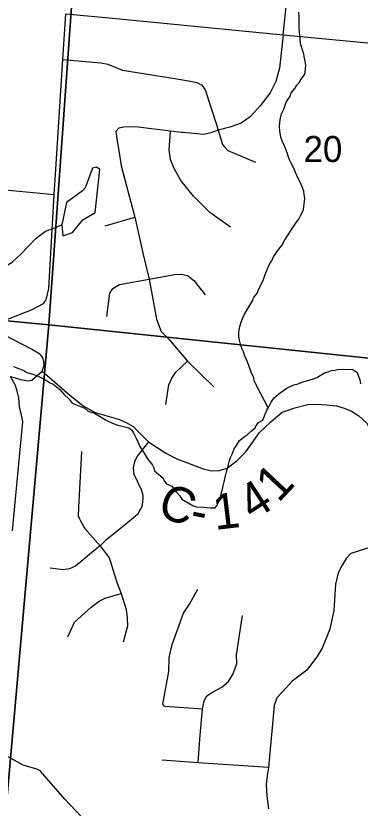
# Model space of a CAD drawing. Extents: x 0 to 34, y -2 to 22.
# Drawn here: x 3.329 to 3.881, y 18.207 to 19.479 of the extents above; entities that cross this region are included whole.
import ezdxf

# ---------------------------------------------------------------- set-up
doc = ezdxf.new("R2010")
doc.units = 0
for name, color, linetype in [('GM_X_County_Road', 7, 'Continuous'), ('GM_X_County_Road_Text', 7, 'Continuous'), ('GM_X_Minor_Lake', 7, 'Continuous'), ('GM_X_Minor_River', 7, 'Continuous'), ('GM_X_Section', 7, 'Continuous'), ('GM_X_Section_Text', 7, 'Continuous'), ('GM_X_Township_Road', 7, 'Continuous')]:
    doc.layers.add(name, color=color, linetype=linetype)

msp = doc.modelspace()

# ---------------------------------------------------------------- linework, layer by layer
at = {"layer": 'GM_X_County_Road'}
for p, q in [((3.4093, 19.4828), (3.4788, 19.4761)), ((3.4788, 19.4761), (3.7574, 19.4492))]:
    msp.add_line(p, q, dxfattribs=at)
for points in [[(3.3764, 19.0222), (3.3785, 19.0257), (3.382, 19.0419), (3.3907, 19.1924), (3.3925, 19.2247), (3.4045, 19.4092), (3.4093, 19.4828)], [(3.7574, 19.4492), (3.7687, 19.4481), (3.9381, 19.4318), (4.0026, 19.4257), (4.0072, 19.4252), (4.0934, 19.4164), (4.1461, 19.4103), (4.1935, 19.4056), (4.2871, 19.3945), (4.3454, 19.3876), (4.3544, 19.3865)], [(3.2954, 18.9847), (3.2957, 18.9857), (3.298, 18.9872), (3.3198, 18.9941), (3.3543, 19.0075), (3.3733, 19.0175), (3.3749, 19.0196), (3.3759, 19.0213), (3.3764, 19.0222)], [(3.3715, 18.9091), (3.3743, 18.9185), (3.374, 18.9246), (3.3728, 18.9294), (3.3698, 18.934), (3.3693, 18.9347), (3.3678, 18.9363), (3.3542, 18.9444), (3.2968, 18.974), (3.2952, 18.9755), (3.295, 18.9775), (3.2948, 18.9828), (3.2951, 18.9838), (3.2954, 18.9847)], [(3.3205, 18.9003), (3.3385, 18.8951), (3.3495, 18.8937), (3.3545, 18.8947), (3.3715, 18.9091)], [(3.3715, 18.9091), (3.383, 18.8987), (3.4151, 18.871), (3.4368, 18.8533), (3.4563, 18.8427), (3.4934, 18.832), (3.5061, 18.8267), (3.517, 18.8203), (3.5285, 18.809), (3.5418, 18.7955), (3.5694, 18.7772), (3.5873, 18.7682), (3.6309, 18.7519), (3.6432, 18.7489), (3.6549, 18.7495), (3.6679, 18.7535), (3.6839, 18.7655), (3.6976, 18.7795), (3.7195, 18.8103), (3.7365, 18.8263), (3.7378, 18.8276), (3.7421, 18.8312)], [(3.324, 18.6527), (3.3401, 18.8282), (3.3382, 18.8386), (3.3352, 18.8516), (3.3338, 18.866), (3.3315, 18.8768), (3.3284, 18.886), (3.3205, 18.9003)], [(3.7421, 18.8312), (3.7562, 18.843), (3.7765, 18.8503), (3.7971, 18.8553), (3.8116, 18.856), (3.8271, 18.8551), (3.8429, 18.8535), (3.8553, 18.8497), (3.8669, 18.8447), (3.8788, 18.8371), (3.8917, 18.8257), (3.9038, 18.8021), (3.9148, 18.7904), (3.9229, 18.7837), (3.9307, 18.7777), (3.9401, 18.7751), (3.9526, 18.7757), (3.9665, 18.7827), (3.9977, 18.799)], [(3.4549, 18.1718), (3.4521, 18.1749), (3.4075, 18.2217), (3.3688, 18.2666), (3.3673, 18.2678), (3.3628, 18.2699), (3.3411, 18.2766), (3.3169, 18.29)]]:
    msp.add_lwpolyline(points, dxfattribs=at)
at = {"layer": 'GM_X_Minor_Lake'}
for points in [[(3.4199, 19.1315), (3.4364, 19.1519), (3.4561, 19.1636), (3.4636, 19.2329), (3.4584, 19.2365), (3.4519, 19.2348), (3.4417, 19.2077), (3.4404, 19.2031), (3.4358, 19.1987), (3.4102, 19.18), (3.4031, 19.1439)], [(3.4031, 19.1439), (3.4042, 19.1262), (3.4199, 19.1315)]]:
    msp.add_lwpolyline(points, dxfattribs=at)
at = {"layer": 'GM_X_Minor_River'}
for points in [[(3.7335, 18.85), (3.7152, 18.8851), (3.7113, 18.8939), (3.7104, 18.8985), (3.7065, 18.9074), (3.703, 18.9163), (3.6999, 18.9251), (3.6964, 18.9332), (3.6939, 18.9398), (3.6918, 18.9444), (3.6897, 18.9502), (3.6874, 18.9586), (3.6864, 18.964), (3.6867, 18.9708), (3.6881, 18.9806), (3.6903, 18.9878), (3.6924, 18.9934), (3.6952, 18.9994), (3.6981, 19.005), (3.7041, 19.0151), (3.7089, 19.0225), (3.7102, 19.0266), (3.7162, 19.0348), (3.7183, 19.04), (3.7231, 19.049), (3.726, 19.0561), (3.7286, 19.064), (3.7336, 19.076), (3.7364, 19.082), (3.7392, 19.0861), (3.7421, 19.0924), (3.7469, 19.0995), (3.7509, 19.1047), (3.7553, 19.111), (3.7605, 19.1199), (3.7669, 19.1292), (3.7722, 19.1381), (3.7786, 19.1474), (3.7825, 19.153), (3.7858, 19.1597), (3.7903, 19.1683), (3.7909, 19.1736), (3.7919, 19.1812), (3.7921, 19.1865), (3.7915, 19.1926), (3.7906, 19.1979), (3.7881, 19.2049), (3.785, 19.2126), (3.7814, 19.2184), (3.7793, 19.223), (3.7772, 19.2281), (3.7748, 19.235), (3.7712, 19.2419), (3.768, 19.247), (3.7659, 19.2524), (3.7638, 19.2593), (3.7597, 19.2705), (3.7561, 19.279), (3.7541, 19.2847), (3.7521, 19.2947), (3.7516, 19.3015), (3.7522, 19.3084), (3.7532, 19.3155), (3.755, 19.3223), (3.7587, 19.3298), (3.7625, 19.3407), (3.7689, 19.3504), (3.7702, 19.3556), (3.7765, 19.3626), (3.7793, 19.3679), (3.7837, 19.373), (3.7873, 19.3794), (3.7905, 19.3834), (3.7929, 19.3879), (3.7936, 19.3947), (3.7937, 19.3997), (3.7928, 19.4065), (3.7919, 19.4115), (3.7906, 19.418), (3.7861, 19.433), (3.7849, 19.4406), (3.7847, 19.4456), (3.7838, 19.4521), (3.783, 19.4624), (3.783, 19.4723), (3.7831, 19.4772), (3.7826, 19.4852)], [(3.1967, 19.076), (3.2167, 19.0801), (3.2277, 19.0809), (3.2402, 19.0802), (3.2508, 19.0772), (3.2639, 19.0726), (3.2763, 19.0681), (3.2896, 19.0654), (3.3026, 19.0715), (3.3123, 19.0773), (3.3231, 19.0839), (3.3372, 19.0968), (3.3493, 19.1097), (3.3615, 19.1223), (3.3766, 19.134), (3.39, 19.1386), (3.4031, 19.1439)], [(3.3256, 18.9164), (3.3417, 18.9102), (3.3465, 18.9066), (3.3563, 18.904), (3.3623, 18.9022), (3.3739, 18.8969), (3.3843, 18.8901), (3.3888, 18.888), (3.3995, 18.8796), (3.4061, 18.8718), (3.4145, 18.8639), (3.4196, 18.8577), (3.4301, 18.8535), (3.4395, 18.8494), (3.445, 18.845), (3.4551, 18.8416), (3.4685, 18.8335), (3.473, 18.8311), (3.4771, 18.8287), (3.4838, 18.8254), (3.4928, 18.8221), (3.5038, 18.8198), (3.5101, 18.818), (3.515, 18.8145), (3.5182, 18.809), (3.5214, 18.8024), (3.5249, 18.7955), (3.5281, 18.7878), (3.5346, 18.7773), (3.5403, 18.7683), (3.545, 18.7621), (3.5479, 18.7578), (3.5501, 18.7536), (3.5514, 18.749), (3.5651, 18.7371), (3.5668, 18.7328), (3.5708, 18.7281), (3.579, 18.7244), (3.5834, 18.7182), (3.5878, 18.7139), (3.5918, 18.7088), (3.595, 18.7033), (3.6055, 18.6977), (3.6107, 18.6944), (3.6148, 18.6924), (3.6189, 18.6911), (3.6303, 18.6907), (3.6412, 18.6896), (3.6485, 18.6893), (3.652, 18.6941), (3.6537, 18.6983), (3.6566, 18.7043), (3.658, 18.7122), (3.6605, 18.7193), (3.6619, 18.7269), (3.6636, 18.7333), (3.665, 18.7408), (3.6668, 18.7472), (3.6689, 18.7551), (3.6711, 18.7634), (3.6733, 18.7706), (3.6757, 18.7758), (3.6791, 18.7844), (3.6827, 18.7896), (3.6875, 18.7975), (3.6949, 18.8037), (3.7, 18.8069), (3.7062, 18.8124), (3.7129, 18.8179), (3.7145, 18.822), (3.7181, 18.8264), (3.7251, 18.8304), (3.7264, 18.8345), (3.7288, 18.8397), (3.7313, 18.8465), (3.7345, 18.8517), (3.7386, 18.8592), (3.7434, 18.8662), (3.7505, 18.8724), (3.7579, 18.8779)], [(3.7579, 18.8779), (3.7625, 18.8811), (3.7745, 18.8868), (3.7818, 18.8888), (3.7891, 18.892), (3.7994, 18.8943), (3.8079, 18.8971), (3.8125, 18.8992), (3.8238, 18.9064), (3.8295, 18.9081), (3.8349, 18.9098), (3.8406, 18.9104), (3.8448, 18.9117), (3.854, 18.9122), (3.8691, 18.9117), (3.8762, 18.9069), (3.8807, 18.8953), (3.8816, 18.8884)]]:
    msp.add_lwpolyline(points, dxfattribs=at)
at = {"layer": 'GM_X_Section'}
for points in [[(3.4541, 19.9967), (3.3818, 18.9832), (2.3398, 19.083), (2.4387, 20.1012)], [(3.4541, 19.9967), (4.4338, 19.8873), (4.3356, 18.8839), (3.3818, 18.9832)], [(2.3398, 19.083), (3.3818, 18.9832), (3.2914, 17.96), (2.2302, 18.1283)], [(4.3356, 18.8839), (4.2197, 17.8557), (3.2914, 17.96), (3.3818, 18.9832)]]:
    msp.add_lwpolyline(points, close=True, dxfattribs=at)
at = {"layer": 'GM_X_Township_Road'}
msp.add_line((3.4721, 19.1423), (3.5196, 19.1562), dxfattribs=at)
for points in [[(3.7574, 19.4492), (3.7634, 19.5046), (3.7674, 19.5258), (3.7662, 19.5389), (3.7591, 19.555), (3.7485, 19.5676), (3.7348, 19.575), (3.7023, 19.5935), (3.692, 19.6131), (3.6904, 19.6215), (3.6899, 19.6322), (3.6927, 19.6411), (3.6975, 19.6517), (3.7039, 19.6585), (3.7131, 19.6642), (3.7384, 19.6715)], [(3.7574, 19.4492), (3.7517, 19.3955), (3.7457, 19.3743), (3.737, 19.3558), (3.7209, 19.3348), (3.7049, 19.3172), (3.6902, 19.3074), (3.672, 19.3009), (3.6534, 19.2958), (3.6419, 19.2918), (3.6304, 19.2892), (3.5966, 19.2923)], [(3.4045, 19.4092), (3.4655, 19.4039), (3.4768, 19.402), (3.5, 19.3921), (3.5841, 19.3788), (3.609, 19.3746), (3.6192, 19.3724), (3.6274, 19.3679), (3.6328, 19.3609), (3.6511, 19.3033), (3.6534, 19.2958), (3.6606, 19.273), (3.6639, 19.2684), (3.669, 19.2632), (3.7132, 19.2447)], [(3.5966, 19.2923), (3.5946, 19.2924), (3.577, 19.2944), (3.5254, 19.3006), (3.5093, 19.3011), (3.5024, 19.3007), (3.4944, 19.2992), (3.4896, 19.2937)], [(3.4896, 19.2937), (3.4914, 19.2783), (3.4941, 19.2631), (3.4978, 19.2389), (3.5196, 19.1562), (3.5334, 19.0965)], [(3.673, 19.14), (3.64, 19.1639), (3.6136, 19.1902), (3.5935, 19.2152), (3.5827, 19.2345), (3.5772, 19.2486), (3.575, 19.2636), (3.577, 19.2944)], [(3.2117, 19.1568), (3.2167, 19.2041), (3.219, 19.2059), (3.2229, 19.2081), (3.226, 19.208), (3.2271, 19.2079), (3.3001, 19.201), (3.3907, 19.1924)], [(3.5334, 19.0965), (3.5426, 19.0568), (3.5543, 18.9927), (3.5622, 18.9727), (3.5739, 18.9609), (3.6041, 18.9251), (3.6463, 18.8836)], [(3.4751, 18.9967), (3.4799, 19.034), (3.4844, 19.0419), (3.495, 19.0481), (3.5426, 19.0568), (3.5834, 19.0644), (3.5944, 19.0646), (3.6043, 19.0624), (3.6146, 19.0546), (3.6323, 19.0316)], [(3.5696, 18.8556), (3.5745, 18.8868), (3.5791, 18.8977), (3.5858, 18.9072), (3.6041, 18.9251)], [(3.5418, 18.7955), (3.5298, 18.7807), (3.5234, 18.7724), (3.5191, 18.7635), (3.5173, 18.7536), (3.5181, 18.7436), (3.5298, 18.7188), (3.5326, 18.7101), (3.5327, 18.7048), (3.5322, 18.6992), (3.5309, 18.6911), (3.5241, 18.6787), (3.5021, 18.6608), (3.494, 18.6541)], [(3.4341, 18.78), (3.4305, 18.7098), (3.4293, 18.6906), (3.4292, 18.6757), (3.4306, 18.6732), (3.433, 18.6688)], [(3.433, 18.6688), (3.4399, 18.6564), (3.4641, 18.6284), (3.4785, 18.6094), (3.4812, 18.6014), (3.4842, 18.5922)], [(3.494, 18.6541), (3.4881, 18.6492), (3.4728, 18.637), (3.4641, 18.6284), (3.4507, 18.6177), (3.4371, 18.6059), (3.4246, 18.5959), (3.4151, 18.5916), (3.4048, 18.5902), (3.384, 18.5928)], [(3.9787, 18.6604), (3.9758, 18.6511), (3.8663, 18.6165), (3.8583, 18.6084), (3.8519, 18.5974), (3.8458, 18.585), (3.8417, 18.5672), (3.839, 18.5245), (3.8326, 18.495), (3.82, 18.4641), (3.8128, 18.4518), (3.7953, 18.4288), (3.7721, 18.4115), (3.7563, 18.3943), (3.7472, 18.3844), (3.7463, 18.3815)], [(3.4842, 18.5922), (3.4917, 18.5685), (3.4978, 18.5519), (3.5057, 18.5264), (3.5078, 18.5132), (3.5081, 18.4994), (3.5012, 18.4739)], [(3.4125, 18.4827), (3.4231, 18.5062), (3.4498, 18.5302), (3.4626, 18.5395), (3.4724, 18.5445), (3.4978, 18.5519)], [(3.6283, 18.3665), (3.5686, 18.3704), (3.5667, 18.3712), (3.5655, 18.3726), (3.5649, 18.3743), (3.5741, 18.4269), (3.5751, 18.4494), (3.5799, 18.4704), (3.5977, 18.5202), (3.6073, 18.535), (3.6206, 18.559)], [(3.624, 18.3189), (3.6283, 18.3665), (3.631, 18.3797), (3.6355, 18.3876), (3.6452, 18.3942), (3.6593, 18.4017), (3.67, 18.4107), (3.6773, 18.4228), (3.6832, 18.4394), (3.6828, 18.4533), (3.6924, 18.5168)], [(3.7463, 18.3815), (3.743, 18.372), (3.7341, 18.2725), (3.7327, 18.2632)], [(3.6215, 18.2804), (3.6239, 18.3179), (3.624, 18.3189)], [(3.7341, 18.2725), (3.6215, 18.2804), (3.5635, 18.2847)], [(3.7327, 18.2632), (3.7301, 18.2453), (3.7315, 18.2274), (3.734, 18.2065)]]:
    msp.add_lwpolyline(points, dxfattribs=at)

# ---------------------------------------------------------------- texts
at = {"layer": 'GM_X_County_Road_Text'}
for s, rotation, p in [('1', 46.8807, (3.7498, 18.6963)), ('C', 339.937, (3.5535, 18.6777)), ('4', 33.1304, (3.7094, 18.6677)), ('1', 6.8718, (3.6484, 18.6539)), ('-', 348.5189, (3.606, 18.6593))]:
    msp.add_text(s, height=0.0568, rotation=rotation, dxfattribs=at).set_placement(p)
at = {"layer": 'GM_X_Section_Text'}
msp.add_text('20', height=0.04186, rotation=0, dxfattribs=at).set_placement((3.7902, 19.2447))

doc.saveas('drawing.dxf')
